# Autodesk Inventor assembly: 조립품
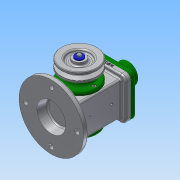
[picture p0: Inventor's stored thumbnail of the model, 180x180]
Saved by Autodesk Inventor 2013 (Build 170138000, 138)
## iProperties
Created: 2018-10
Part Number: 조립품
Document SubType Name: Assembly
Designer: Administrator
Author: Administrator
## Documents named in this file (18)
- C:\Users\Administrator\Desktop\새폴더\481007V1065\조립품.iam
- C:\Users\Administrator\Desktop\새폴더\481007V1065\E-링.ipt
- C:\Users\Administrator\Desktop\새폴더\481007V1065\V-벨트풀리.ipt
- C:\Users\Administrator\Desktop\새폴더\481007V1065\덮개.ipt
- C:\Users\Administrator\Desktop\새폴더\481007V1065\뒤커버.ipt
- C:\Users\Administrator\Desktop\새폴더\481007V1065\링크.ipt
- C:\Users\Administrator\Desktop\새폴더\481007V1065\베어링 17 x 40 x 12.ipt
- C:\Users\Administrator\Desktop\새폴더\481007V1065\본체.ipt
- C:\Users\Administrator\Desktop\새폴더\481007V1065\볼트 M4 x 8.ipt
- C:\Users\Administrator\Desktop\새폴더\481007V1065\볼트 M4 x 10.ipt
- C:\Users\Administrator\Desktop\새폴더\481007V1065\슬라이더.ipt
- C:\Users\Administrator\Desktop\새폴더\481007V1065\앞커버.ipt
- C:\Users\Administrator\Desktop\새폴더\481007V1065\오일 실 17 30 8.ipt
- C:\Users\Administrator\Desktop\새폴더\481007V1065\와셔 4x16.ipt
- C:\Users\Administrator\Desktop\새폴더\481007V1065\클레비스 핀 6 x 22.ipt
- 클레비스 핀 6 x 22.ipt
- C:\Users\Administrator\Desktop\새폴더\481007V1065\키 4 x 4 x 12.ipt
- C:\Users\Administrator\Desktop\새폴더\481007V1065\편심축.ipt
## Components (2 placed, 2 different names)
1. E-링:1
2. V-벨트풀리:1
